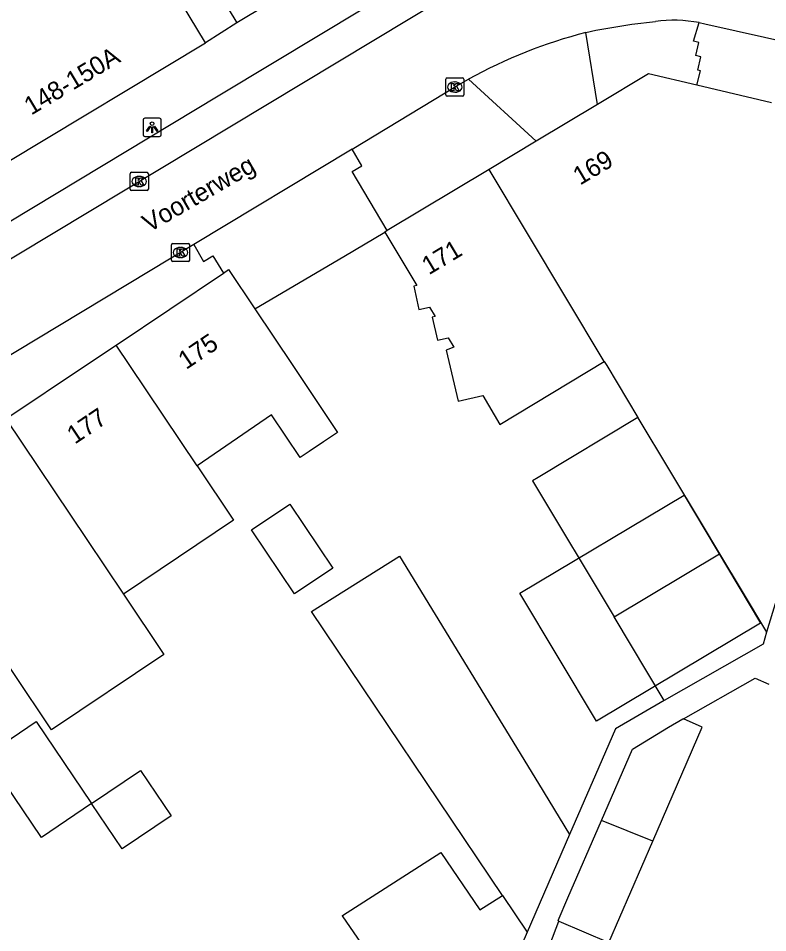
# Model space of a CAD drawing. Extents: x 161771 to 163125, y 382479 to 383177.
# Drawn here: x 162407.6 to 162448.8, y 382718.9 to 382769.1 of the extents above; entities that cross this region are included whole.
import ezdxf

# ---------------------------------------------------------------- set-up
doc = ezdxf.new("R2010")
doc.units = 0
for name, color, linetype in [('IMGEO_Kolk', 7, 'Continuous'), ('IMGEO_Lichtpunt', 7, 'Continuous'), ('IMGEO_Openbare_ruimte_label', 7, 'Continuous'), ('IMGEO_Pand', 7, 'Continuous'), ('IMGEO_Pand_nummerreeks', 7, 'Continuous'), ('IMGEO_Pand_vergunning_verleend', 7, 'Continuous'), ('IMGEO_Rijbaan_lokaal_open', 7, 'Continuous'), ('IMGEO_Voetpad_open', 7, 'Continuous')]:
    doc.layers.add(name, color=color, linetype=linetype)

msp = doc.modelspace()

# ---------------------------------------------------------------- linework, layer by layer
at = {"layer": 'IMGEO_Kolk'}
for p, q in [((162431.088, 382764.86), (162431.088, 382765.712)), ((162431.163, 382765.786), (162432.015, 382765.786)), ((162431.576, 382765.566), (162431.601, 382765.566)), ((162432.089, 382765.712), (162432.089, 382764.86)), ((162432.015, 382764.786), (162431.163, 382764.786)), ((162431.599, 382765.006), (162431.574, 382765.006)), ((162413.836, 382760.608), (162414.688, 382760.608)), ((162413.761, 382759.682), (162413.761, 382760.534)), ((162414.249, 382760.388), (162414.274, 382760.388)), ((162414.762, 382760.534), (162414.762, 382759.682)), ((162414.688, 382759.608), (162413.836, 382759.608)), ((162414.272, 382759.828), (162414.247, 382759.828)), ((162416.029, 382755.781), (162416.029, 382756.633)), ((162416.104, 382756.707), (162416.956, 382756.707)), ((162417.03, 382756.633), (162417.03, 382755.781)), ((162416.517, 382756.487), (162416.542, 382756.487)), ((162416.956, 382755.707), (162416.104, 382755.707)), ((162416.54, 382755.927), (162416.515, 382755.927))]:
    msp.add_line(p, q, dxfattribs=at)
for points in [[(162431.088, 382764.86), (162431.088, 382765.712)], [(162431.163, 382765.786), (162432.015, 382765.786)], [(162432.089, 382765.712), (162432.089, 382764.86)], [(162431.409, 382765.486), (162431.532, 382765.486), (162431.532, 382765.335), (162431.662, 382765.486), (162431.826, 382765.486), (162431.68, 382765.335), (162431.833, 382765.086), (162431.681, 382765.086), (162431.596, 382765.25), (162431.532, 382765.183), (162431.532, 382765.086), (162431.409, 382765.086), (162431.409, 382765.486)], [(162432.015, 382764.786), (162431.163, 382764.786)], [(162413.836, 382760.608), (162414.688, 382760.608)], [(162413.761, 382759.682), (162413.761, 382760.534)], [(162414.082, 382760.308), (162414.205, 382760.308), (162414.205, 382760.157), (162414.335, 382760.308), (162414.499, 382760.308), (162414.353, 382760.157), (162414.506, 382759.908), (162414.354, 382759.908), (162414.269, 382760.072), (162414.205, 382760.005), (162414.205, 382759.908), (162414.082, 382759.908), (162414.082, 382760.308)], [(162414.762, 382760.534), (162414.762, 382759.682)], [(162414.688, 382759.608), (162413.836, 382759.608)], [(162416.029, 382755.781), (162416.029, 382756.633)], [(162416.104, 382756.707), (162416.956, 382756.707)], [(162417.03, 382756.633), (162417.03, 382755.781)], [(162416.35, 382756.407), (162416.473, 382756.407), (162416.473, 382756.256), (162416.603, 382756.407), (162416.767, 382756.407), (162416.621, 382756.256), (162416.774, 382756.007), (162416.622, 382756.007), (162416.537, 382756.171), (162416.473, 382756.104), (162416.473, 382756.007), (162416.35, 382756.007), (162416.35, 382756.407)], [(162416.956, 382755.707), (162416.104, 382755.707)]]:
    msp.add_lwpolyline(points, dxfattribs=at)
for centre, start, end in [((162431.165, 382765.71), 91.552, 178.448), ((162431.165, 382765.71), 91.552, 178.448), ((162432.013, 382765.71), 1.552, 88.448), ((162432.013, 382765.71), 1.552, 88.448), ((162431.165, 382764.862), 181.552, 268.448), ((162431.165, 382764.862), 181.552, 268.448), ((162432.013, 382764.862), 271.552, 358.448), ((162432.013, 382764.862), 271.552, 358.448), ((162413.838, 382760.532), 91.552, 178.448), ((162413.838, 382760.532), 91.552, 178.448), ((162414.686, 382760.532), 1.552, 88.448), ((162414.686, 382760.532), 1.552, 88.448), ((162413.838, 382759.684), 181.552, 268.448), ((162413.838, 382759.684), 181.552, 268.448), ((162414.686, 382759.684), 271.552, 358.448), ((162414.686, 382759.684), 271.552, 358.448), ((162416.106, 382756.631), 91.552, 178.448), ((162416.106, 382756.631), 91.552, 178.448), ((162416.954, 382756.631), 1.552, 88.448), ((162416.954, 382756.631), 1.552, 88.448), ((162416.106, 382755.783), 181.552, 268.448), ((162416.106, 382755.783), 181.552, 268.448), ((162416.954, 382755.783), 271.552, 358.448), ((162416.954, 382755.783), 271.552, 358.448)]:
    msp.add_arc(centre, 0.0765, start, end, dxfattribs=at)
for centre, major_axis, ratio, start_param, end_param in [((162431.575, 382765.286), (-0.387, 0.002), 0.722429, 4.712389, 7.853982), ((162431.6, 382765.286), (-0.39, 0.002), 0.717154, 1.570796, 4.712389), ((162414.248, 382760.108), (-0.387, 0.002), 0.722429, 4.712389, 7.853982), ((162414.273, 382760.108), (-0.39, 0.002), 0.717154, 1.570796, 4.712389), ((162416.516, 382756.207), (-0.387, 0.002), 0.722429, 4.712389, 7.853982), ((162416.541, 382756.207), (-0.39, 0.002), 0.717154, 1.570796, 4.712389)]:
    msp.add_ellipse(centre, major_axis=major_axis, ratio=ratio, start_param=start_param, end_param=end_param, dxfattribs=at)
at = {"layer": 'IMGEO_Lichtpunt'}
for p, q in [((162415.372, 382763.575), (162414.564, 382763.575)), ((162415.372, 382763.575), (162414.564, 382763.575)), ((162414.47, 382763.48), (162414.47, 382762.673)), ((162414.47, 382763.48), (162414.47, 382762.673)), ((162415.466, 382762.673), (162415.466, 382763.48)), ((162415.466, 382762.673), (162415.466, 382763.48)), ((162414.564, 382762.579), (162415.372, 382762.579)), ((162414.564, 382762.579), (162415.372, 382762.579))]:
    msp.add_line(p, q, dxfattribs=at)
for points in [[(162414.844, 382763.144), (162414.883, 382763.116), (162414.695, 382762.854), (162414.657, 382762.881), (162414.844, 382763.144)], [(162414.946, 382763.096), (162414.993, 382763.096), (162414.993, 382762.774), (162414.946, 382762.774), (162414.946, 382763.096)], [(162415.056, 382763.116), (162415.094, 382763.143), (162415.281, 382762.881), (162415.242, 382762.853), (162415.056, 382763.116)]]:
    msp.add_lwpolyline(points, dxfattribs=at)
msp.add_circle((162414.969, 382763.278), 0.0994, dxfattribs=at)
for centre, start, end in [((162414.564, 382763.48), 90, 180), ((162414.564, 382763.48), 90, 180), ((162415.372, 382763.48), 0, 90), ((162415.372, 382763.48), 0, 90), ((162414.564, 382762.673), 180, 270), ((162414.564, 382762.673), 180, 270), ((162415.372, 382762.673), 270, 0), ((162415.372, 382762.673), 270, 360)]:
    msp.add_arc(centre, 0.0946, start, end, dxfattribs=at)
at = {"layer": 'IMGEO_Pand'}
for points in [[(162417.896, 382767.709), (162415.322, 382771.996), (162413.579, 382774.899), (162405.913, 382787.488), (162401.729, 382784.934), (162397.721, 382791.12), (162391.452, 382787.091), (162401.036, 382771.125)], [(162416.256, 382785.452), (162414.552, 382784.43), (162414.082, 382784.148), (162416.772, 382779.665), (162414.075, 382778.046), (162417.047, 382773.095), (162419.621, 382768.808)], [(162424.488, 382771.73), (162419.621, 382768.808)], [(162407.01, 382761.174), (162417.896, 382767.709)], [(162444.87, 382765.387), (162442.217, 382766.01), (162439.427, 382764.337)], [(162448.975, 382764.422), (162444.87, 382765.387)], [(162439.427, 382764.337), (162436.047, 382762.31)], [(162456.838, 382762.564), (162453.079, 382750), (162449.225, 382737.119), (162448.701, 382735.368)], [(162436.047, 382762.31), (162433.468, 382760.763)], [(162433.468, 382760.763), (162427.874, 382757.408)], [(162439.792, 382750.222), (162433.468, 382760.763)], [(162427.874, 382757.408), (162427.736, 382757.325)], [(162427.736, 382757.325), (162429.496, 382754.391), (162429.333, 382754.355), (162429.615, 382753.086), (162430.201, 382753.216), (162430.51, 382752.701), (162430.346, 382752.665), (162430.629, 382751.396), (162431.214, 382751.526), (162431.523, 382751.012), (162431.117, 382750.846), (162431.761, 382748.052), (162433.117, 382748.353), (162434.063, 382746.776), (162439.792, 382750.222)], [(162412.991, 382751.128), (162418.882, 382755.079)], [(162418.882, 382755.079), (162419.163, 382755.267), (162420.609, 382753.111)], [(162420.609, 382753.111), (162422.696, 382750), (162425.151, 382746.339), (162424.37, 382745.815), (162423.59, 382745.292), (162423.092, 382744.958), (162421.519, 382747.303), (162417.433, 382744.505)], [(162406.945, 382747.074), (162411.308, 382750), (162412.991, 382751.128)], [(162417.433, 382744.505), (162413.747, 382750), (162412.991, 382751.128)], [(162439.792, 382750.222), (162439.925, 382750), (162441.639, 382747.144)], [(162406.945, 382747.074), (162411.385, 382740.449), (162413.391, 382737.457)], [(162441.639, 382747.144), (162436.162, 382743.858), (162435.853, 382743.672), (162440.331, 382736.206)], [(162441.639, 382747.144), (162441.64, 382747.142), (162445.115, 382741.349), (162446.118, 382739.676)], [(162417.433, 382744.505), (162419.437, 382741.512), (162413.391, 382737.457)], [(162413.391, 382737.457), (162415.612, 382734.144), (162409.444, 382730.009), (162405.218, 382736.314), (162403.562, 382738.785), (162400.777, 382742.938)], [(162420.42, 382740.994), (162422.526, 382742.406), (162424.883, 382738.891), (162422.778, 382737.479), (162420.42, 382740.994)], [(162434.198, 382720.924), (162423.713, 382736.498), (162423.727, 382736.507), (162428.549, 382739.539), (162436.175, 382727.065), (162437.886, 382724.267)], [(162440.331, 382736.206), (162446.118, 382739.676)], [(162446.118, 382739.676), (162447.307, 382737.693), (162448.701, 382735.368)], [(162443.083, 382731.617), (162440.331, 382736.206)], [(162448.701, 382735.368), (162448.504, 382734.708), (162443.083, 382731.617)], [(162411.639, 382725.962), (162408.888, 382724.105), (162405.849, 382728.607), (162408.6, 382730.465), (162411.639, 382725.962)], [(162439.637, 382725.033), (162441.336, 382728.947), (162443.322, 382730.154), (162444.098, 382730.625), (162444.131, 382730.611)], [(162442.456, 382723.91), (162445.169, 382730.16), (162444.131, 382730.611)], [(162411.639, 382725.962), (162414.33, 382727.779), (162416.007, 382725.296), (162413.316, 382723.479), (162411.639, 382725.962)], [(162437.301, 382719.522), (162437.253, 382719.543), (162437.798, 382720.799), (162439.637, 382725.033)], [(162442.456, 382723.91), (162439.637, 382725.033)], [(162437.886, 382724.267), (162435.557, 382718.902)], [(162437.301, 382719.522), (162440.036, 382718.335), (162442.456, 382723.91)], [(162430.146, 382712.932), (162429.747, 382713.513), (162429.515, 382713.851), (162425.423, 382719.812), (162425.416, 382719.822), (162430.817, 382723.279), (162432.966, 382720.134), (162434.198, 382720.924)], [(162434.198, 382720.924), (162435.557, 382718.902)], [(162435.557, 382718.902), (162431.873, 382710.416)]]:
    msp.add_lwpolyline(points, dxfattribs=at)
at = {"layer": 'IMGEO_Pand_vergunning_verleend'}
msp.add_lwpolyline([(162435.159, 382737.51), (162444.172, 382742.89), (162448.366, 382735.863), (162439.354, 382730.483), (162435.159, 382737.51)], dxfattribs=at)
at = {"layer": 'IMGEO_Rijbaan_lokaal_open'}
for points in [[(162436.924, 382773.757), (162401.714, 382752.548)], [(162438.784, 382768.279), (162439.33, 382768.413), (162441.31, 382768.747), (162442.595, 382768.893)], [(162444.998, 382768.824), (162445.302, 382768.763), (162450.304, 382767.649)], [(162425.943, 382761.883), (162431.665, 382765.333), (162432.338, 382765.718)], [(162425.943, 382761.883), (162417.253, 382756.645)], [(162417.253, 382756.645), (162406.234, 382750), (162404.03, 382748.676)]]:
    msp.add_lwpolyline(points, dxfattribs=at)
for centre, radius, start, end in [((162443.571, 382761.015), 7.938, 79.6457, 97.0648), ((162445.514, 382741.948), 27.177, 104.3365, 118.9994)]:
    msp.add_arc(centre, radius, start, end, dxfattribs=at)
at = {"layer": 'IMGEO_Voetpad_open'}
for points in [[(162398.211, 382752.528), (162418.589, 382764.804), (162421.673, 382766.662), (162436.082, 382775.342)], [(162419.621, 382768.808), (162417.896, 382767.709)], [(162444.87, 382765.387), (162445.073, 382766.171), (162444.918, 382766.207), (162445.086, 382766.949), (162444.81, 382767.013), (162444.985, 382767.738), (162444.694, 382767.809), (162444.998, 382768.824)], [(162439.427, 382764.337), (162438.784, 382768.279)], [(162432.338, 382765.718), (162436.047, 382762.31)], [(162427.874, 382757.408), (162425.947, 382760.649), (162426.473, 382760.96), (162425.943, 382761.883)], [(162420.609, 382753.111), (162425.493, 382755.98), (162427.736, 382757.325)], [(162417.253, 382756.645), (162417.795, 382755.717), (162418.307, 382756.03), (162418.882, 382755.079)], [(162444.131, 382730.611), (162448.076, 382732.842), (162448.823, 382732.519)], [(162443.083, 382731.617), (162440.402, 382730.062), (162439.312, 382727.552), (162437.886, 382724.267)], [(162436.794, 382718.219), (162437.301, 382719.522)]]:
    msp.add_lwpolyline(points, dxfattribs=at)

# ---------------------------------------------------------------- texts
at = {"layer": 'IMGEO_Openbare_ruimte_label'}
msp.add_text('Voorterweg', height=1, rotation=30.0503, dxfattribs=at).set_placement((162414.806, 382757.289))
at = {"layer": 'IMGEO_Pand_nummerreeks'}
for s, rotation, p in [('148-150A', 30.9741, (162408.33, 382763.716)), ('169', 30.7965, (162438.457, 382759.875)), ('171', 30.9512, (162430.161, 382754.954)), ('175', 33.8446, (162416.834, 382749.756)), ('177', 33.8448, (162410.725, 382745.66))]:
    msp.add_text(s, height=1, rotation=rotation, dxfattribs=at).set_placement(p)

doc.saveas('drawing.dxf')
